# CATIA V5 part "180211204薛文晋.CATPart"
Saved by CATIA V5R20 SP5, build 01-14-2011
Part number: Part1
Bounding box of the stored display mesh (mm): x -51.986 to 51.986, y 0 to 65, z -51.986 to 51.986
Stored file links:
  E:\wolun.CATPart
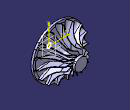
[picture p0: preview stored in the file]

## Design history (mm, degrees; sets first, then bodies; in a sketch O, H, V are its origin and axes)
Body1 (main body)
  Sketch1 on xy-plane, origin (0, 0, 0), H (1, 0, 0), V (0, 1, 0)
    point P1 (12.5, 60)
    line L1 (12.5, 60) -> (12.5, 65)
    line L2 (12.5, 65) -> (0, 65)
    point P3 (0, 65)
    line L3 (0, 65) -> (0, 0)
    line L4 (0, 0) -> (12.5, 0)
    point P4 (12.5, 0)
    line L5 (12.5, 0) -> (12.5, 16)
    line L6 (12.5, 16) -> (52, 16)
    line L7 (52, 16) -> (52, 20)
    line L8 (52, 20) -> (47, 20)
    point P8 (47, 20)
    spline S1 through (12.5, 60) (26.9353, 24.9886) (47, 20)
    point P9 (47, 20)
    point P10 (12.5, 60)
    length L2 = 12.5
    length L3 = 65
    length L1 = 5
    length L8 = 5
    length L7 = 4
    length L5 = 16
    distance L3 L7 = 52
    vertical: L1 V, L3 V, L5 V, L7 V
    coincidence: P3 V, P4 L1, P9 L8, P10 P1, P9 P8
    horizontal: L2 H, L4 H, L6 H, L8 H
    tangency: S1 L8, S1 L1
  Shaft1: profile Sketch1, axis Sketch1.L3, angle 360
  Sketch2 on xy-plane, origin (0, 0, 0), H (1, 0, 0), V (0, 1, 0)
    point P1 (0, 45)
    line L1 (0, 45) -> (0, 27)
    arc A1 centre (7, 27) radius 7 from (0, 27) to (7, 20) ccw
    point P4 (7, 20)
    arc A2 centre (-19.5714, 45) radius 19.5714 from (0, 45) to (-7, 60) ccw
    point P6 (-7, 60)
    reference projected line E1 (12.5, 65) -> (-12.5, 65) from edge [face of Shaft1 from Sketch1.L2 | face of Shaft1 from Sketch1.L1]
    axis line L2 (7, 27) -> (7, 20)
    reference projected line E2 (52, 20) -> (-52, 20) from edge [face of Shaft1 from Sketch1.L8 | face of Shaft1 from Sketch1.L7]
    reference projected line E3 (52, 20) -> (-52, 20) from edge [face of Shaft1 from Sketch1.L8 | face of Shaft1 from Sketch1.L7]
    distance P6 P1 V = 15
    distance P1 E1 = 20
    distance P6 P1 H = 7
    radius A1 = 7
    coincidence: P1 V, P4 E3
    vertical: L1 V, L2 V
    tangency: A1 L1, A2 L1
    perpendicularity: L2 E2
  Pad1: profile Sketch2, direction (0, 0, 1), length 50, thin wall 0, second thickness 1
  CircPattern1: of the body so far, instances 15, angular step 24, axis from face of Shaft1 from Sketch1.L6
  Sketch3 on xy-plane, origin (0, 0, 0), H (1, 0, 0), V (0, 1, 0)
    circle A1 centre (51.4067, 60) radius 30
    point P1 (51.4067, 60)
    reference projected line E1 through (0, 0) direction (0, -1) from axis of face of CircPattern1
    reference projected line E2 (11.0311, 60) -> (50.4578, 60) from edge [face of CircPattern1 | face of CircPattern1]
    radius A1 = 30
    distance E1 P1 = 51.4067
    coincidence: P1 E2
  Groove1: profile Sketch3, axis axis of face of CircPattern1, angle 360
  Sketch4 on zx-plane, origin (0, 0, 0), H (-1, 0, 0), V (0, 0, 1)
    circle A1 centre (0, 0) radius 6.9011
    line L1 (-0.6321, 4.5015) -> (-0.6321, 8.2812)
    point P2 (-0.6321, 8.2812)
    line L2 (-0.6321, 8.2812) -> (0.5679, 8.2812)
    point P3 (0.5679, 8.2812)
    line L3 (0.5679, 8.2812) -> (0.5679, 4.5015)
    distance P2 P3 = 1.2
    vertical: L1 V, L3 V
    horizontal: L2 H
  Sketch5 on zx-plane, origin (0, 0, 0), H (-1, 0, 0), V (0, 0, 1)
    circle A1 centre (0, 0) radius 3.5
    point P1 (-0.6, 3.4482)
    line L1 (-0.6, 3.4482) -> (-0.6, 4.6482)
    line L2 (-0.6, 4.6482) -> (0.6, 4.6482)
    line L3 (0.6, 4.6482) -> (0.6, 3.4482)
    point P4 (0.6, 3.4482)
    circle A2 centre (0, 0) radius 3.5
    circle A3 centre (0, 0) radius 3.5
    circle A4 centre (0, 0) radius 3.5
    circle A5 centre (0, 0) radius 3.5
    circle A6 centre (0, 0) radius 3.5
    circle A7 centre (0, 0) radius 3.5
    circle A8 centre (0, 0) radius 3.5
    circle A9 centre (0, 0) radius 3.5
    circle A10 centre (0, 0) radius 3.5
    circle A11 centre (0, 0) radius 3.5
    circle A12 centre (0, 0) radius 3.5
    circle A13 centre (0, 0) radius 3.5
    circle A14 centre (0, 0) radius 3.5
    circle A15 centre (0, 0) radius 3.5
    circle A16 centre (0, 0) radius 3.5
    line L4 (-3.7254, 2.8437) -> (-2.6862, 2.2437)
    line L5 (-4.3254, 1.8045) -> (-3.7254, 2.8437)
    line L6 (-3.2862, 1.2045) -> (-4.3254, 1.8045)
    circle A17 centre (0, 0) radius 3.5
    line L7 (-4.3254, -1.8045) -> (-3.2862, -1.2045)
    line L8 (-3.7254, -2.8437) -> (-4.3254, -1.8045)
    line L9 (-2.6862, -2.2437) -> (-3.7254, -2.8437)
    circle A18 centre (0, 0) radius 3.5
    line L10 (-0.6, -4.6482) -> (-0.6, -3.4482)
    line L11 (0.6, -4.6482) -> (-0.6, -4.6482)
    line L12 (0.6, -3.4482) -> (0.6, -4.6482)
    arc A19 centre (0, 0) radius 3.5 from (-2.6862, -2.2437) to (-3.2862, -1.2045) ccw
    line L13 (3.7254, -2.8437) -> (2.6862, -2.2437)
    line L14 (4.3254, -1.8045) -> (3.7254, -2.8437)
    line L15 (3.2862, -1.2045) -> (4.3254, -1.8045)
    arc A20 centre (0, 0) radius 3.5 from (-2.6862, -2.2437) to (-3.2862, -1.2045) ccw
    line L16 (4.3254, 1.8045) -> (3.2862, 1.2045)
    line L17 (3.7254, 2.8437) -> (4.3254, 1.8045)
    line L18 (2.6862, 2.2437) -> (3.7254, 2.8437)
    arc A21 centre (0, 0) radius 3.5 from (-3.4468, -0.6078) to (-3.2862, -1.2045) ccw
    point P45 (-2.2498, 2.6812)
    arc A22 centre (0, 0) radius 3.5 from (0.6, -3.4482) to (-2.6862, 2.2437) ccw
    arc A23 centre (0, 0) radius 3.5 from (-2.6862, -2.2437) to (-0.6, -3.4482) ccw
    length L2 = 1.2
    length L3 = 1.2
    radius A1 = 3.5
    length L1 = 1.2
    coincidence: P1 A1, P4 A1
    vertical: L1 V, L3 V
    horizontal: L2 H
  Sketch6 on zx-plane, origin (0, 0, 0), H (-1, 0, 0), V (0, 0, 1)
